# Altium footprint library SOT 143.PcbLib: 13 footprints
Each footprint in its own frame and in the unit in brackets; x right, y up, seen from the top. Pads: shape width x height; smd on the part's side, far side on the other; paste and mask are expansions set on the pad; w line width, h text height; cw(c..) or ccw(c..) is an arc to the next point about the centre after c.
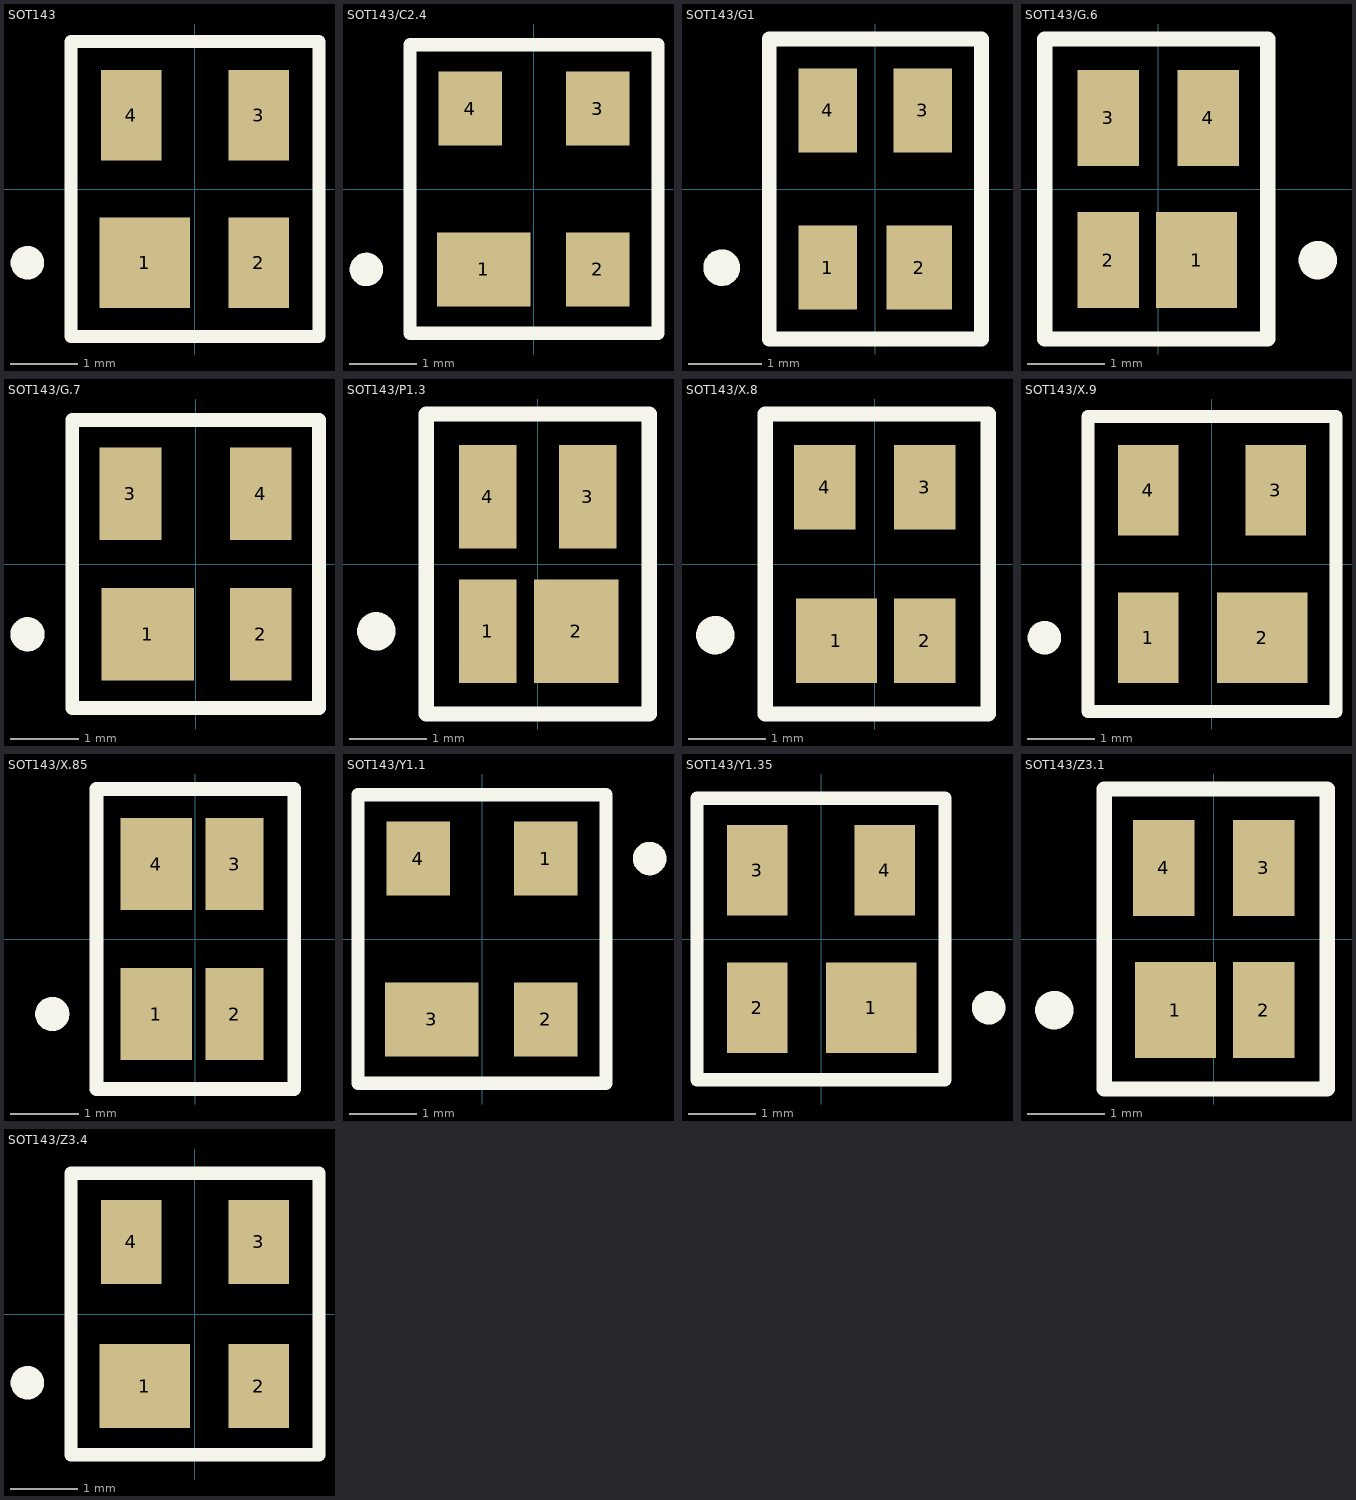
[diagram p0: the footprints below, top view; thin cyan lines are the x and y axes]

## SOT143 [mm]
pads (4):
  rect 1.35x1.35 smd: 1(-0.75,-1.1)
  rect 0.9x1.35 smd: 2(0.95,-1.1) 3(0.95,1.1) 4(-0.95,1.1)
Top Overlay:
  circle w0.25: c-2.5,-1.1 r0.125
  lines w0.2: -1.85,-2.2 1.85,-2.2 1.85,2.2 -1.85,2.2 -1.85,-2.2

## SOT143/C2.4 [mm]
pads (4):
  rect 1.4x1.1 smd: 1(-0.75,-1.2)
  rect 0.95x1.1 smd: 2(0.95,-1.2) 3(0.95,1.2) 4(-0.95,1.2)
Top Overlay:
  circle w0.25: c-2.5,-1.2 r0.125
  lines w0.2: -1.85,-2.15 -1.85,2.15 1.85,2.15 1.85,-2.15 -1.85,-2.15

## SOT143/G1 [mm]
pads (4):
  rect 0.8x1.15 smd: 1(-0.65,-1.075) 3(0.65,1.075) 4(-0.65,1.075)
  rect 0.9x1.15 smd: 2(0.6,-1.075)
Top Overlay:
  circle w0.25: c-2.1,-1.075 r0.125
  lines w0.2: -1.45,-2.05 1.45,-2.05 1.45,2.05 -1.45,2.05 -1.45,-2.05

## SOT143/G.6 [mm]
pads (4):
  rect 1.05x1.25 smd: 1(0.5,-0.925)
  rect 0.8x1.25 smd: 2(-0.65,-0.925) 3(-0.65,0.925) 4(0.65,0.925)
Top Overlay:
  circle w0.25: c2.075,-0.925 r0.125
  lines w0.2: -1.475,-1.95 1.425,-1.95 1.425,1.95 -1.475,1.95 -1.475,-1.95

## SOT143/G.7 [mm]
pads (4):
  rect 1.35x1.35 smd: 1(-0.7,-1.025)
  rect 0.9x1.35 smd: 2(0.95,-1.025) 3(-0.95,1.025) 4(0.95,1.025)
Top Overlay:
  circle w0.25: c-2.45,-1.025 r0.125
  lines w0.2: -1.8,-2.1 1.8,-2.1 1.8,2.1 -1.8,2.1 -1.8,-2.1

## SOT143/P1.3 [mm]
pads (4):
  rect 0.75x1.35 smd: 1(-0.65,-0.875) 3(0.65,0.875) 4(-0.65,0.875)
  rect 1.1x1.35 smd: 2(0.5,-0.875)
Top Overlay:
  circle w0.25: c-2.1,-0.875 r0.125
  lines w0.2: -1.45,-1.95 -1.45,1.95 1.45,1.95 1.45,-1.95 -1.45,-1.95

## SOT143/X.8 [mm]
pads (4):
  rect 1.05x1.1 smd: 1(-0.5,-1)
  rect 0.8x1.1 smd: 2(0.65,-1) 3(0.65,1) 4(-0.65,1)
Top Overlay:
  circle w0.25: c-2.075,-0.925 r0.125
  lines w0.2: -1.425,-1.95 1.475,-1.95 1.475,1.95 -1.425,1.95 -1.425,-1.95

## SOT143/X.9 [mm]
pads (4):
  rect 0.9x1.35 smd: 1(-0.95,-1.1) 3(0.95,1.1) 4(-0.95,1.1)
  rect 1.35x1.35 smd: 2(0.75,-1.1)
Top Overlay:
  circle w0.25: c-2.5,-1.1 r0.125
  lines w0.2: -1.85,-2.2 -1.85,2.2 1.85,2.2 1.85,-2.2 -1.85,-2.2

## SOT143/X.85 [mm]
pads (4):
  rect 1.05x1.35 smd: 1(-0.575,-1.1) 4(-0.575,1.1)
  rect 0.85x1.35 smd: 2(0.575,-1.1) 3(0.575,1.1)
Top Overlay:
  circle w0.25: c-2.1,-1.1 r0.125
  lines w0.2: -1.45,-2.2 -1.45,2.2 1.45,2.2 1.45,-2.2 -1.45,-2.2

## SOT143/Y1.1 [mm]
pads (4):
  rect 0.95x1.1 smd: 1(0.95,1.2) 2(0.95,-1.2) 4(-0.95,1.2)
  rect 1.4x1.1 smd: 3(-0.75,-1.2)
Top Overlay:
  circle w0.25: c2.5,1.2 r0.125
  lines w0.2: -1.85,-2.15 1.85,-2.15 1.85,2.15 -1.85,2.15 -1.85,-2.15

## SOT143/Y1.35 [mm]
pads (4):
  rect 1.35x1.35 smd: 1(0.75,-1.025)
  rect 0.9x1.35 smd: 2(-0.95,-1.025) 3(-0.95,1.025) 4(0.95,1.025)
Top Overlay:
  circle w0.25: c2.5,-1.025 r0.125
  lines w0.2: -1.85,-2.1 1.85,-2.1 1.85,2.1 -1.85,2.1 -1.85,-2.1

## SOT143/Z3.1 [mm]
pads (4):
  rect 1.05x1.25 smd: 1(-0.5,-0.925)
  rect 0.8x1.25 smd: 2(0.65,-0.925) 3(0.65,0.925) 4(-0.65,0.925)
Top Overlay:
  circle w0.25: c-2.075,-0.925 r0.125
  lines w0.2: -1.425,-1.95 1.475,-1.95 1.475,1.95 -1.425,1.95 -1.425,-1.95

## SOT143/Z3.4 [mm]
pads (4):
  rect 1.35x1.25 smd: 1(-0.75,-1.075)
  rect 0.9x1.25 smd: 2(0.95,-1.075) 3(0.95,1.075) 4(-0.95,1.075)
Top Overlay:
  circle w0.25: c-2.5,-1.025 r0.125
  lines w0.2: -1.85,-2.1 1.85,-2.1 1.85,2.1 -1.85,2.1 -1.85,-2.1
